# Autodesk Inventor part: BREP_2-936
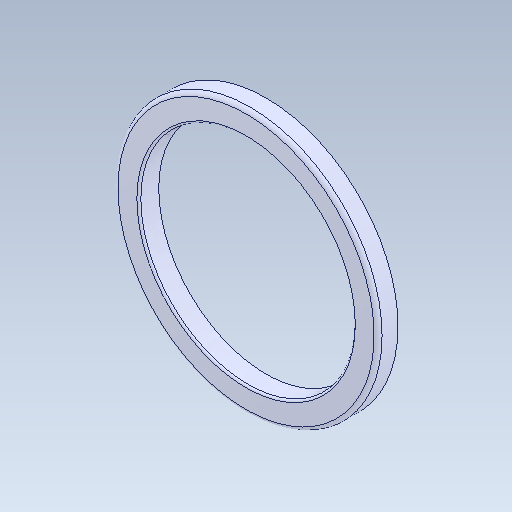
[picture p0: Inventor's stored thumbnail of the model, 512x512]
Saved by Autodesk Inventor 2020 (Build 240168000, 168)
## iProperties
Created: 2017-09
Part Number: BREP_2-936
Material: Générique
Document SubType Name: Modeling
Designer: bruno
Density: 1 g/cm^3
Appearance: Par défaut
Author: bruno
Sending System: SolidWorks 2016
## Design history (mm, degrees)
feature "Importée1"
node "Solide1"
